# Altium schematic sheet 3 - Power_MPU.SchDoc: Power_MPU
size A3; CompanyName: Octavo Systtems LLC; Address3: Austin,TX; Address4: USA; DocumentNumber: DK2 RefDes; Revision: C-01; SheetNumber: 3; SheetTotal: 14
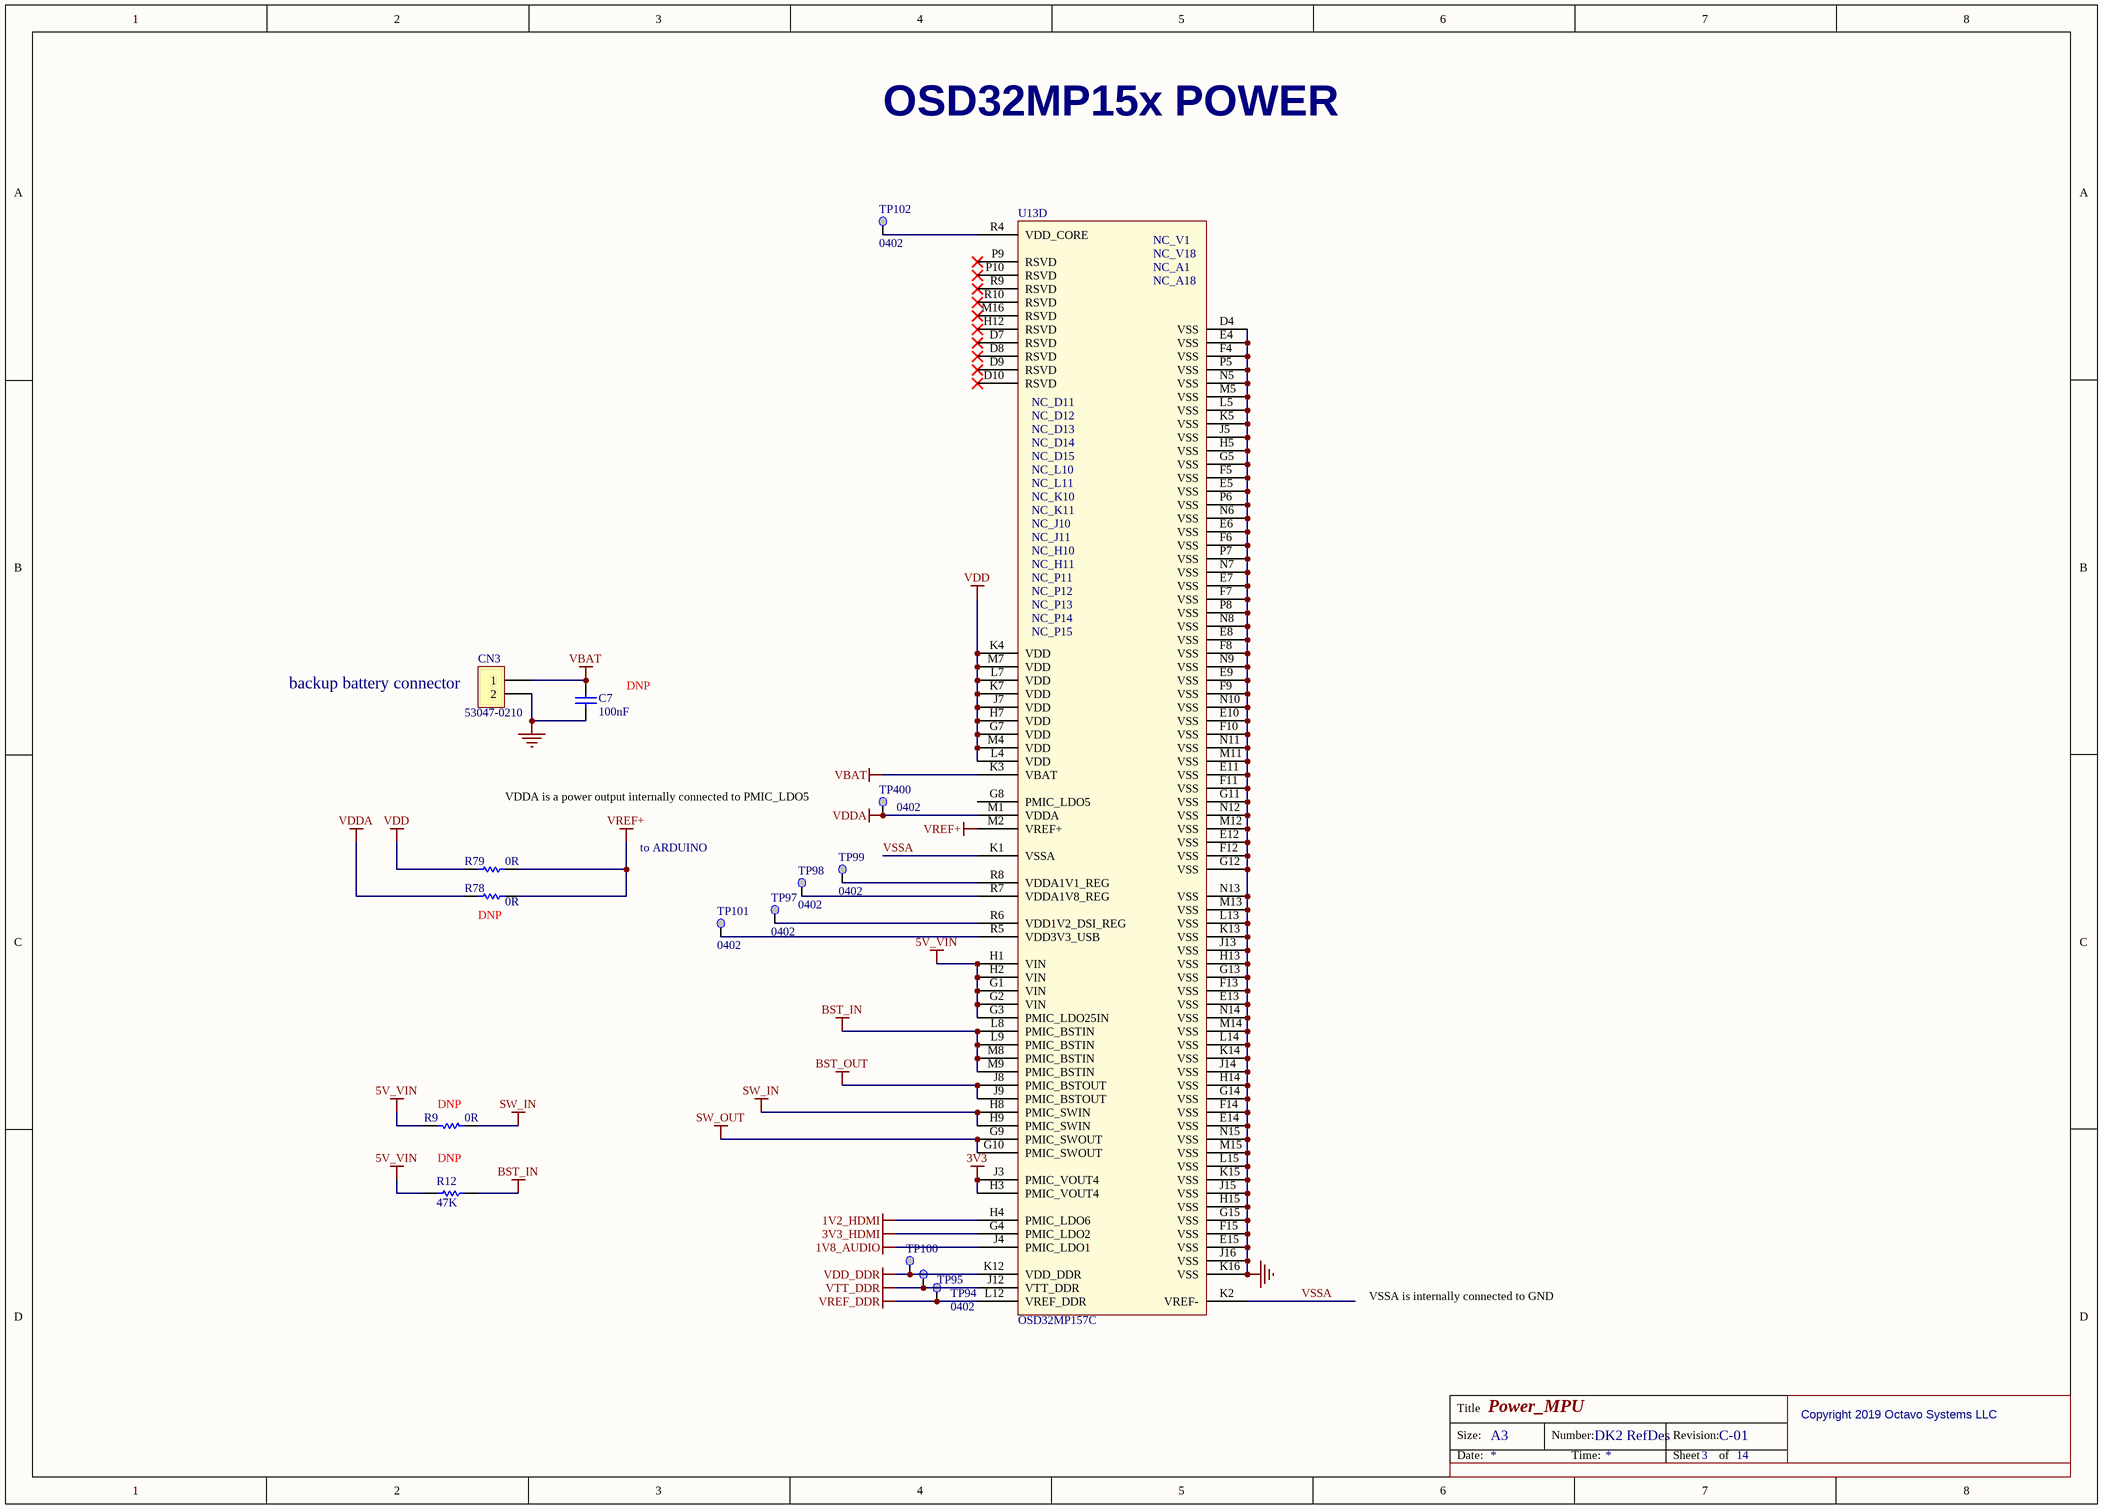
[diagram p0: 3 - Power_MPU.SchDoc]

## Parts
C7  value 100nF  [C0402]  (no BOM)
CN3  value 53047-0210  [CON_MOLEX_53047-0210]
R9  value 0R  [R0402]  (no BOM)
R12  value 47K  [R0402]  (hidden comment: Resistor)  (no BOM)
R78  value 0R  [R0402]  (no BOM)
R79  value 0R  [R0402]
TP94  0402  [TP]
TP95  0402  [TP]  (value not drawn)
TP97  0402  [TP]
TP98  0402  [TP]
TP99  0402  [TP]
TP100  0402  [TP]  (value not drawn)
TP101  0402  [TP]
TP102  0402  [TP]
TP400  0402  [TP]
U13  OSD32MP157C  [ICC_BGA324_18X18_OSD32MP157CAC3]  (part D of 4)

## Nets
1V2_HDMI: U13.H4(PMIC_LDO6)
1V8_AUDIO: U13.J4(PMIC_LDO1)
3V3: U13.H3(PMIC_VOUT4) U13.J3(PMIC_VOUT4)
3V3_HDMI: U13.G4(PMIC_LDO2)
5V_VIN: R9.1 R12.2 U13.G1(VIN) U13.G2(VIN) U13.G3(PMIC_LDO25IN) U13.H1(VIN) U13.H2(VIN)
BST_IN: R12.1 U13.L8(PMIC_BSTIN) U13.L9(PMIC_BSTIN) U13.M8(PMIC_BSTIN) U13.M9(PMIC_BSTIN)
BST_OUT: U13.J8(PMIC_BSTOUT) U13.J9(PMIC_BSTOUT)
GND: C7.1 CN3.2 U13.D4(VSS) U13.E4(VSS) U13.E5(VSS) U13.E6(VSS) U13.E7(VSS) U13.E8(VSS) U13.E9(VSS) U13.E10(VSS) U13.E11(VSS) U13.E12(VSS) U13.E13(VSS) U13.E14(VSS) U13.E15(VSS) U13.F4(VSS) U13.F5(VSS) U13.F6(VSS) U13.F7(VSS) U13.F8(VSS) U13.F9(VSS) U13.F10(VSS) U13.F11(VSS) U13.F12(VSS) U13.F13(VSS) U13.F14(VSS) U13.F15(VSS) U13.G5(VSS) U13.G11(VSS) U13.G12(VSS) U13.G13(VSS) U13.G14(VSS) U13.G15(VSS) U13.H5(VSS) U13.H13(VSS) U13.H14(VSS) U13.H15(VSS) U13.J5(VSS) U13.J13(VSS) U13.J14(VSS) U13.J15(VSS) U13.J16(VSS) U13.K5(VSS) U13.K13(VSS) U13.K14(VSS) U13.K15(VSS) U13.K16(VSS) U13.L5(VSS) U13.L13(VSS) U13.L14(VSS) U13.L15(VSS) U13.M5(VSS) U13.M11(VSS) U13.M12(VSS) U13.M13(VSS) U13.M14(VSS) U13.M15(VSS) U13.N5(VSS) U13.N6(VSS) U13.N7(VSS) U13.N8(VSS) U13.N9(VSS) U13.N10(VSS) U13.N11(VSS) U13.N12(VSS) U13.N13(VSS) U13.N14(VSS) U13.N15(VSS) U13.P5(VSS) U13.P6(VSS) U13.P7(VSS) U13.P8(VSS)
SW_IN: R9.2 U13.H8(PMIC_SWIN) U13.H9(PMIC_SWIN)
SW_OUT: U13.G9(PMIC_SWOUT) U13.G10(PMIC_SWOUT)
VBAT: C7.2 CN3.1 U13.K3(VBAT)
VDD: R79.1 U13.G7(VDD) U13.H7(VDD) U13.J7(VDD) U13.K4(VDD) U13.K7(VDD) U13.L4(VDD) U13.L7(VDD) U13.M4(VDD) U13.M7(VDD)
VDD_DDR: TP100.1 U13.K12(VDD_DDR)
VDDA: R78.1 TP400.1 U13.M1(VDDA)
VREF+: R78.2 R79.2 U13.M2(VREF+)
VREF_DDR: TP94.1 U13.L12(VREF_DDR)
VTT_DDR: TP95.1 U13.J12(VTT_DDR)
VSSA: U13.K1(VSSA) U13.K2(VREF-)
NetTP97_1: TP97.1 U13.R6(VDD1V2_DSI_REG)
NetTP98_1: TP98.1 U13.R7(VDDA1V8_REG)
NetTP99_1: TP99.1 U13.R8(VDDA1V1_REG)
NetTP101_1: TP101.1 U13.R5(VDD3V3_USB)
NetTP102_1: TP102.1 U13.R4(VDD_CORE)

Not connected (* = marked no-connect by the designer): U13 D7(RSVD)* D8(RSVD)* D9(RSVD)* D10(RSVD)* G8(PMIC_LDO5) H12(RSVD)* M16(RSVD)* P9(RSVD)* P10(RSVD)* R9(RSVD)* R10(RSVD)*

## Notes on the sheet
- OSD32MP15x POWER
- (near CN3) backup battery connector
- (near C7) DNP
- VDDA is a power output internally connected to PMIC_LDO5
- to ARDUINO
- (near R78) DNP
- (near R9) DNP
- DNP
- VSSA is internally connected to GND
- Copyright 2019 Octavo Systems LLC

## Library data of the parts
C7 = MCD-00006: Capacitor,100nF,16V,X7R,10%,0402; Manufacturer_Part_Number: CC0402KRX7R7BB104; Manufacturer: YAGEO; Provided_By: Subcon; Initial_Board_Reference: MB1274
CN3 = MCD-00655: Header 2 circuits, 1.25mm Pitch ,  Vertical, with Friction Lock; Part_Type: Connector; Manufacturer: MOLEX; Provided_By: Subcon; Initial_Board_Reference: MB1272
R9 = MCD-00052: Resistor,0R,0402,5%,1/16W; Manufacturer_Part_Number: RC0402JR-070RL; Manufacturer: YAGEO; Provided_By: Subcon; Initial_Board_Reference: mb1274
R12 = MCD-00063: Resistor,47K,0402,1%,1/16W; Manufacturer_Part_Number: RC0402FR-0747KL; Manufacturer: YAGEO; Provided_By: Subcon; Initial_Board_Reference: MB1274
R78 = MCD-00052: Resistor,0R,0402,5%,1/16W; Manufacturer_Part_Number: RC0402JR-070RL; Manufacturer: YAGEO; Provided_By: Subcon; Initial_Board_Reference: MB1274
R79 = MCD-00052: Resistor,0R,0402,5%,1/16W; Manufacturer_Part_Number: RC0402JR-070RL; Manufacturer: YAGEO; Provided_By: Subcon; Initial_Board_Reference: MB1274; Fitted: NO
TP94 TP95 TP97-TP102 TP400 = TP: Testpoint
U13 = OSD32MP157C: MPU 18x18 SIP; Part_Type: IC; Manufacturer: Octavo; ECCN_US: TBD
